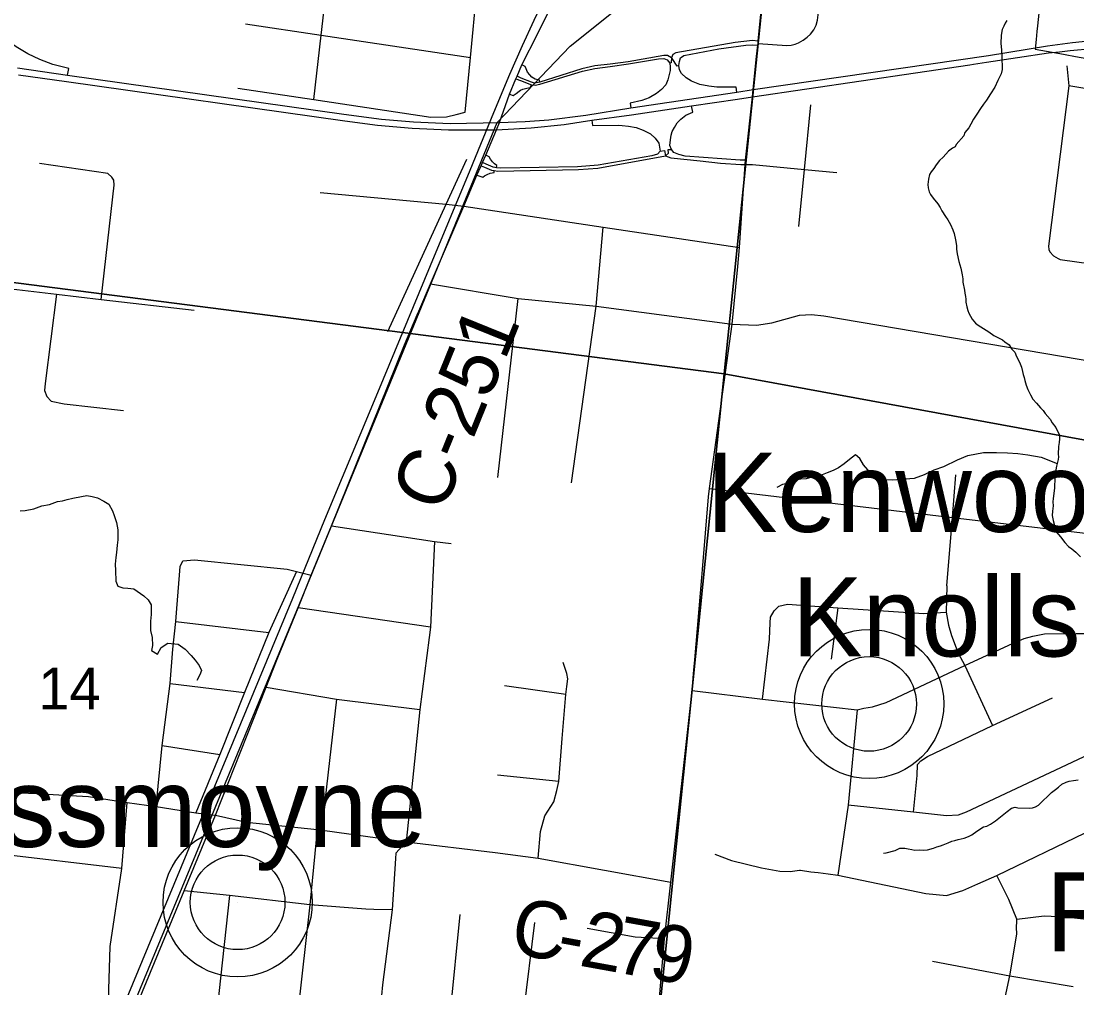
# Model space of a CAD drawing. Extents: x 0 to 34, y -3.9 to 26.2.
# Drawn here: x 6.42 to 7.473, y 18.325 to 19.289 of the extents above; entities that cross this region are included whole.
import ezdxf

# ---------------------------------------------------------------- set-up
doc = ezdxf.new("R2010")
doc.units = 0
for name, color, linetype in [('GM_X_City_Street', 7, 'Continuous'), ('GM_X_County_Road', 7, 'Continuous'), ('GM_X_County_Road_Text', 7, 'Continuous'), ('GM_X_Interchange_Ramps', 7, 'Continuous'), ('GM_X_Minor_River', 7, 'Continuous'), ('GM_X_Rail_Line', 7, 'Continuous'), ('GM_X_Section', 7, 'Continuous'), ('GM_X_Section_Text', 7, 'Continuous'), ('GM_X_State_Route', 7, 'Continuous'), ('GM_X_Township_Road', 7, 'Continuous'), ('GM_X_Unincorporated', 7, 'Continuous'), ('GM_X_Unincorporated_Location', 7, 'Continuous'), ('GM_X_Unincorporated_Text', 7, 'Continuous')]:
    doc.layers.add(name, color=color, linetype=linetype)

msp = doc.modelspace()

# ---------------------------------------------------------------- linework, layer by layer
at = {"layer": 'GM_X_City_Street'}
msp.add_line((6.8951, 18.8339), (6.9155, 19.0126), dxfattribs=at)
for points in [[(7.1548, 19.267), (7.1832, 19.2648), (7.1877, 19.2651), (7.1915, 19.2663), (7.195, 19.2676), (7.1995, 19.2702), (7.2035, 19.2732), (7.2068, 19.2763), (7.2102, 19.2805), (7.2126, 19.2852), (7.2139, 19.29), (7.2147, 19.2955), (7.2286, 19.4323), (7.234, 19.4893)], [(6.8626, 19.1982), (6.8677, 19.2528), (6.8741, 19.3198), (6.8742, 19.321), (6.8806, 19.3716), (6.8938, 19.4782)], [(6.7117, 19.2109), (6.719, 19.2751), (6.7265, 19.3416)], [(6.6434, 19.2864), (6.719, 19.2751), (6.8677, 19.2528)], [(7.4626, 19.2445), (7.4644, 19.2247), (7.4442, 19.0647), (7.4445, 19.0615), (7.4456, 19.059), (7.4493, 19.0551), (7.4538, 19.0523), (7.456, 19.0515), (7.5153, 19.0432), (7.5808, 19.0341)], [(6.6357, 19.2224), (6.7117, 19.2109), (6.8283, 19.1932), (6.8439, 19.1936), (6.8534, 19.1961), (6.8626, 19.1982)], [(7.1062, 18.8228), (7.3484, 18.7941), (7.5235, 18.7734), (7.5317, 18.7746), (7.5375, 18.7779), (7.5412, 18.782), (7.5438, 18.7876), (7.5456, 18.7937), (7.5494, 18.8142), (7.5668, 18.9363), (7.5808, 19.0341), (7.6028, 19.1866), (7.6024, 19.1906), (7.6003, 19.1962), (7.5982, 19.1995), (7.5948, 19.202), (7.5838, 19.2045), (7.4644, 19.2247)], [(7.1954, 19.0844), (7.201, 19.141), (7.2074, 19.2057)], [(6.4996, 19.0115), (6.5126, 19.1255), (6.512, 19.1304), (6.5101, 19.1335), (6.506, 19.137), (6.4379, 19.1472)], [(6.7853, 18.9794), (6.8435, 19.1066), (6.8641, 19.1515)], [(7.1417, 19.1461), (7.1492, 19.1461), (7.201, 19.141), (7.2332, 19.1382)], [(6.7179, 19.1181), (6.8435, 19.1066), (6.8611, 19.1046), (7.0001, 19.0837), (7.1362, 19.0635)], [(6.9687, 18.8286), (6.9931, 19.0047), (7.0001, 19.0837)], [(6.3092, 19.035), (6.3224, 19.0419), (6.3254, 19.0429), (6.3338, 19.0443), (6.3409, 19.0449), (6.3485, 19.0446), (6.3536, 19.0441), (6.358, 19.0431), (6.3655, 19.0405), (6.3726, 19.0363), (6.3843, 19.0283), (6.3878, 19.0264), (6.3929, 19.0251), (6.4096, 19.0221), (6.455, 19.0167), (6.4996, 19.0115), (6.5921, 19.0007)], [(6.8279, 19.0271), (6.9155, 19.0126), (6.9931, 19.0047), (7.1288, 18.987), (7.1531, 18.9858), (7.1683, 18.9883), (7.1959, 18.9957), (7.2078, 18.9965), (7.2201, 18.9953), (7.5668, 18.9363)], [(7.3428, 18.726), (7.3484, 18.7941), (7.3519, 18.8364)]]:
    msp.add_lwpolyline(points, dxfattribs=at)
at = {"layer": 'GM_X_County_Road'}
for p, q in [((7.1548, 19.2692), (7.1598, 19.3192)), ((6.715, 18.4829), (6.7203, 18.4821))]:
    msp.add_line(p, q, dxfattribs=at)
for points in [[(6.9191, 19.2454), (6.9346, 19.2763), (6.9579, 19.3237), (6.9838, 19.3754), (6.9974, 19.4027), (7.0241, 19.4593), (7.0539, 19.5163), (7.1029, 19.6536)], [(7.1494, 19.2172), (7.1498, 19.2209), (7.1532, 19.2538), (7.1543, 19.2651), (7.1548, 19.267), (7.1548, 19.2692)], [(6.8784, 19.1449), (6.8797, 19.148), (6.883, 19.1556), (6.8937, 19.1806), (6.8967, 19.188), (6.9067, 19.2162), (6.9132, 19.2316), (6.9143, 19.2344), (6.9191, 19.2454)], [(7.1344, 19.0444), (7.1362, 19.0635), (7.1417, 19.1461), (7.142, 19.1503), (7.1491, 19.2136), (7.1494, 19.2172)], [(6.8162, 18.9998), (6.8279, 19.0271), (6.8611, 19.1046), (6.8743, 19.1354), (6.8784, 19.1449)], [(7.0992, 18.742), (7.1053, 18.8146), (7.1062, 18.8228), (7.1288, 18.987), (7.1344, 19.0444)], [(6.4488, 18.1059), (6.4496, 18.1078), (6.4657, 18.1464), (6.4931, 18.2096), (6.523, 18.2786), (6.5823, 18.4215), (6.6136, 18.497), (6.664, 18.6248), (6.6751, 18.6528), (6.6959, 18.7039), (6.7091, 18.7364), (6.7291, 18.7856), (6.8019, 18.9663), (6.8146, 18.9962), (6.8162, 18.9998)], [(7.0916, 18.6521), (7.0985, 18.734), (7.0992, 18.742)], [(7.0165, 17.9261), (7.0363, 18.0913), (7.0486, 18.2243), (7.0612, 18.3737), (7.0676, 18.4302), (7.089, 18.6215), (7.0907, 18.6421), (7.0916, 18.6521)], [(6.4173, 18.5195), (6.4192, 18.5194), (6.4349, 18.5188), (6.4628, 18.517), (6.4869, 18.5156), (6.5256, 18.5098), (6.5542, 18.5056), (6.594, 18.4994), (6.6136, 18.497), (6.6443, 18.49), (6.715, 18.4829)], [(6.7203, 18.4821), (6.8036, 18.4705), (6.8923, 18.4598), (6.9354, 18.4542), (7.0676, 18.4302)]]:
    msp.add_lwpolyline(points, dxfattribs=at)
at = {"layer": 'GM_X_Interchange_Ramps'}
for points in [[(7.4353, 19.3035), (7.4333, 19.2843), (7.4327, 19.2787), (7.4319, 19.2707), (7.4309, 19.2612), (7.4592, 19.2561), (7.461, 19.2558), (7.4713, 19.2539), (7.4846, 19.2515)], [(6.466, 19.2354), (6.4671, 19.242), (6.4512, 19.246), (6.4383, 19.251), (6.4265, 19.2564), (6.4148, 19.2634), (6.4054, 19.2701), (6.3984, 19.2761)], [(7.1548, 19.2692), (7.149, 19.2697), (7.1318, 19.2677), (7.0725, 19.2574), (7.0696, 19.2558), (7.0682, 19.2525), (7.068, 19.2477), (7.0665, 19.2472)], [(7.1135, 19.2234), (7.1057, 19.2244), (7.0967, 19.2259), (7.0881, 19.2292), (7.083, 19.2327), (7.0784, 19.2369), (7.0764, 19.2405), (7.0756, 19.2449), (7.0762, 19.2488), (7.0774, 19.2525), (7.0807, 19.255), (7.1155, 19.2614), (7.1425, 19.2653), (7.1489, 19.2655), (7.1543, 19.2651)], [(6.9132, 19.2316), (6.9176, 19.23), (6.9287, 19.2255), (6.9325, 19.2252), (6.937, 19.2263), (6.9796, 19.2392), (6.9919, 19.2419), (7.0073, 19.244), (7.0255, 19.2465), (7.0555, 19.2517), (7.0607, 19.252), (7.0641, 19.2504), (7.0665, 19.2472), (7.0671, 19.2435), (7.0669, 19.2398), (7.0657, 19.2347), (7.0647, 19.2307), (7.0625, 19.2257), (7.0584, 19.2209), (7.0535, 19.2169), (7.0461, 19.2126), (7.0386, 19.21), (7.0271, 19.2074), (7.0276, 19.2025)], [(7.0756, 19.2449), (7.074, 19.2443), (7.0691, 19.2518), (7.0682, 19.2525), (7.0644, 19.255), (7.0607, 19.255), (7.0251, 19.2487), (7.0072, 19.2462), (6.9917, 19.2444), (6.9789, 19.2415), (6.9371, 19.2284), (6.9317, 19.2274), (6.9288, 19.2282), (6.9185, 19.2324), (6.9143, 19.2344)], [(6.9371, 19.2284), (6.9366, 19.2302), (6.9322, 19.2312), (6.9291, 19.2333), (6.9269, 19.2355), (6.9246, 19.2384), (6.9233, 19.2416), (6.9223, 19.2438), (6.9191, 19.2454)], [(6.9067, 19.2162), (6.9105, 19.2149), (6.9133, 19.2171), (6.9163, 19.2193), (6.9177, 19.2202), (6.92, 19.2212), (6.9239, 19.2223), (6.9272, 19.2228), (6.9287, 19.2255)], [(7.1333, 19.2182), (7.1328, 19.2234), (7.1223, 19.2232), (7.1135, 19.2234)], [(7.142, 19.1503), (7.1369, 19.1504), (7.0818, 19.1546), (7.0756, 19.156), (7.0707, 19.1581), (7.0682, 19.1612), (7.0667, 19.1651), (7.0672, 19.1707), (7.068, 19.1754), (7.069, 19.1791), (7.0713, 19.183), (7.0739, 19.1878), (7.0777, 19.1915), (7.0826, 19.1954), (7.0895, 19.1983), (7.0884, 19.2045)], [(6.9888, 19.1905), (6.9894, 19.185), (7.0159, 19.1853), (7.0191, 19.185)], [(7.0191, 19.185), (7.0254, 19.1845), (7.0332, 19.183), (7.0402, 19.1803), (7.0472, 19.1766), (7.0521, 19.1725), (7.0558, 19.1674), (7.0569, 19.1594)], [(6.8784, 19.1449), (6.8817, 19.1435), (6.8887, 19.1406), (6.8915, 19.1401), (6.8951, 19.1395), (6.9756, 19.1411), (6.995, 19.1425), (7.0624, 19.1548), (7.0653, 19.1575), (7.0649, 19.161), (7.0682, 19.1612)], [(7.0569, 19.1594), (7.0542, 19.1565), (7.0486, 19.1547), (6.9952, 19.1456), (6.9746, 19.1439), (6.8982, 19.1424), (6.8937, 19.1429), (6.8906, 19.1435), (6.8836, 19.1465), (6.8797, 19.148)], [(6.8937, 19.1429), (6.894, 19.1453), (6.8918, 19.1468), (6.8898, 19.1487), (6.8878, 19.1515), (6.8866, 19.1538), (6.883, 19.1556)], [(7.0569, 19.1594), (7.0612, 19.1602), (7.0624, 19.1548), (7.0677, 19.1529), (7.0969, 19.1497)], [(7.0969, 19.1497), (7.1171, 19.1474), (7.1375, 19.146), (7.1417, 19.1461)], [(6.8743, 19.1354), (6.88, 19.1336), (6.8819, 19.1349), (6.8846, 19.1363), (6.8873, 19.1374), (6.8915, 19.1381), (6.8915, 19.1401)]]:
    msp.add_lwpolyline(points, dxfattribs=at)
at = {"layer": 'GM_X_Minor_River'}
for points in [[(7.4027, 19.2897), (7.401, 19.2871), (7.3998, 19.2841), (7.3981, 19.2808), (7.3971, 19.2751), (7.3967, 19.2667), (7.3973, 19.2606), (7.3977, 19.2538), (7.3976, 19.2511), (7.3981, 19.2439), (7.398, 19.2408), (7.397, 19.2367), (7.3937, 19.23), (7.3907, 19.2232), (7.3866, 19.2165), (7.3826, 19.2102), (7.3793, 19.2062), (7.3765, 19.2021), (7.3728, 19.1962), (7.3695, 19.1914), (7.3667, 19.1865), (7.365, 19.1828), (7.361, 19.178), (7.3597, 19.1746), (7.3521, 19.1662), (7.3512, 19.1636), (7.3485, 19.1625), (7.3445, 19.1593), (7.3393, 19.1534), (7.3357, 19.1501), (7.3321, 19.1457), (7.33, 19.1423), (7.3272, 19.1387), (7.3256, 19.1361), (7.3246, 19.1315), (7.324, 19.1262), (7.3243, 19.1228), (7.3253, 19.119), (7.3267, 19.1162), (7.3292, 19.1127), (7.3339, 19.1068), (7.3361, 19.1033), (7.3378, 19.0998), (7.3414, 19.0943)], [(7.3414, 19.0943), (7.344, 19.0908), (7.3465, 19.0862), (7.3489, 19.0811), (7.3503, 19.0773), (7.3516, 19.0711), (7.3525, 19.0654), (7.3527, 19.0616), (7.3533, 19.057), (7.3549, 19.0493), (7.3569, 19.0428), (7.3582, 19.0362), (7.3587, 19.032), (7.359, 19.0286), (7.3606, 19.0209), (7.3608, 19.0179), (7.3615, 19.0144), (7.3617, 19.0118), (7.362, 19.0087), (7.3629, 19.0041), (7.3639, 19.0006), (7.365, 18.9979), (7.3682, 18.9917), (7.3714, 18.9878), (7.374, 18.9858), (7.3793, 18.9825), (7.3822, 18.9809), (7.3849, 18.9793), (7.3897, 18.9756), (7.3957, 18.9724), (7.3983, 18.9711), (7.4009, 18.9691), (7.405, 18.9663), (7.4075, 18.9624), (7.4108, 18.9588), (7.4125, 18.9546), (7.4153, 18.9491), (7.4174, 18.9441), (7.4184, 18.9395), (7.419, 18.9368), (7.4201, 18.9337), (7.4207, 18.9307), (7.422, 18.926), (7.4238, 18.9218), (7.4262, 18.9164), (7.4287, 18.9121), (7.4324, 18.9081), (7.4364, 18.9034), (7.439, 18.9007), (7.4411, 18.8979), (7.4459, 18.892), (7.448, 18.8885), (7.4516, 18.8838), (7.4551, 18.876), (7.4554, 18.8726), (7.4548, 18.8688), (7.4543, 18.8647), (7.454, 18.8571), (7.4542, 18.8544), (7.4538, 18.8518), (7.4523, 18.8453), (7.4513, 18.8397), (7.4507, 18.834), (7.4503, 18.8234), (7.4491, 18.8128), (7.4486, 18.8097), (7.4488, 18.8055), (7.4482, 18.8002), (7.448, 18.7961), (7.449, 18.7911), (7.4503, 18.7861), (7.4519, 18.7796), (7.4563, 18.7748), (7.4607, 18.7689), (7.4643, 18.765), (7.4677, 18.7626), (7.4717, 18.7594), (7.4761, 18.7546)], [(7.2747, 18.8323), (7.2886, 18.8317), (7.3012, 18.8326), (7.3107, 18.8332), (7.3206, 18.8368), (7.3302, 18.8416), (7.3398, 18.8448), (7.3536, 18.8514), (7.364, 18.8557), (7.3796, 18.8589), (7.3925, 18.859), (7.4035, 18.8584), (7.4138, 18.8578), (7.4236, 18.8565), (7.4369, 18.8543), (7.4529, 18.848)], [(7.2747, 18.8323), (7.268, 18.836), (7.2641, 18.8415), (7.2597, 18.8466), (7.2562, 18.8528), (7.2517, 18.8564), (7.2459, 18.8517), (7.2404, 18.8474), (7.2349, 18.8435), (7.2295, 18.841), (7.2237, 18.8386), (7.2187, 18.8365), (7.214, 18.8352), (7.2091, 18.8346), (7.2025, 18.8326), (7.1972, 18.8321), (7.1922, 18.8312), (7.1853, 18.8284), (7.1791, 18.8268), (7.1733, 18.824)], [(6.4188, 18.8006), (6.4238, 18.8011), (6.4322, 18.8027), (6.4403, 18.8058), (6.448, 18.807), (6.4561, 18.8101), (6.461, 18.8106), (6.4656, 18.8119), (6.4714, 18.8132), (6.4798, 18.8148), (6.4852, 18.8161), (6.4905, 18.8151), (6.4957, 18.8137), (6.5021, 18.8104), (6.5072, 18.8072), (6.5108, 18.8006), (6.5125, 18.7959), (6.5149, 18.789), (6.5161, 18.7817), (6.5161, 18.7718), (6.5155, 18.7665), (6.5148, 18.759), (6.5143, 18.754), (6.5136, 18.7476), (6.5138, 18.7411), (6.5141, 18.7305), (6.5162, 18.7255), (6.5211, 18.7237), (6.526, 18.7235), (6.532, 18.7229), (6.542, 18.716), (6.5464, 18.712), (6.5493, 18.707), (6.5494, 18.7016), (6.5493, 18.6971), (6.5486, 18.6907), (6.5486, 18.6812), (6.5503, 18.6742), (6.5507, 18.6662), (6.5498, 18.6613), (6.5557, 18.6577), (6.5594, 18.6644), (6.566, 18.6686), (6.5762, 18.6675), (6.5832, 18.6626), (6.5891, 18.6563), (6.5931, 18.6516), (6.5971, 18.6464), (6.5995, 18.6414), (6.5978, 18.6369), (6.5949, 18.6313)], [(7.2796, 18.4593), (7.2823, 18.4596), (7.2912, 18.4619), (7.2959, 18.464), (7.3009, 18.4642), (7.3043, 18.4636), (7.3081, 18.4627), (7.3111, 18.4622), (7.3153, 18.4624), (7.3199, 18.4623), (7.3237, 18.4625), (7.3295, 18.4642), (7.333, 18.4655), (7.3365, 18.4665), (7.3392, 18.4676), (7.3443, 18.4693), (7.3478, 18.471), (7.3509, 18.4717), (7.3543, 18.4727), (7.3601, 18.474), (7.3644, 18.4757), (7.3679, 18.4775), (7.3727, 18.4811), (7.3793, 18.4854), (7.3828, 18.486), (7.3863, 18.4881), (7.3914, 18.4914), (7.3997, 18.4979), (7.4029, 18.5008), (7.4073, 18.504), (7.4111, 18.505), (7.4138, 18.5045), (7.4252, 18.5041), (7.4283, 18.5043), (7.4314, 18.5054), (7.4342, 18.5072), (7.4385, 18.5115), (7.4437, 18.5159), (7.4473, 18.5196), (7.4512, 18.5228), (7.4544, 18.525), (7.4576, 18.5279), (7.4619, 18.53), (7.465, 18.531), (7.4692, 18.5316), (7.4738, 18.5322)]]:
    msp.add_lwpolyline(points, dxfattribs=at)
at = {"layer": 'GM_X_Rail_Line'}
for points in [[(6.4949, 18.2415), (6.5465, 18.3657), (6.6905, 18.7136), (6.7227, 18.792), (6.7755, 18.9187), (6.8279, 19.0453), (6.8674, 19.1406), (6.8911, 19.1979), (6.9071, 19.2364), (6.9196, 19.2649), (6.9312, 19.2902), (6.9677, 19.365), (6.9896, 19.409), (7.0117, 19.4529), (7.0377, 19.5051), (7.0469, 19.5255), (7.0562, 19.5468), (7.0699, 19.5827), (7.0748, 19.5969), (7.098, 19.6602), (7.1178, 19.7152), (7.1979, 19.9367)], [(5.7241, 16.9743), (5.8452, 17.029), (5.873, 17.0335), (5.8979, 17.2837), (6.0426, 17.4881), (6.3175, 17.8683), (6.3835, 17.9611), (6.4086, 18.0098), (6.517, 18.2722), (6.6945, 18.7013), (6.8945, 19.188), (6.9673, 19.2641), (7.0598, 19.3383), (7.1575, 19.4128), (7.1736, 19.4378), (7.1863, 19.6097), (7.204, 19.7377)]]:
    msp.add_lwpolyline(points, dxfattribs=at)
at = {"layer": 'GM_X_Section'}
for points in [[(6.1758, 20.0989), (7.2234, 19.9362), (7.1209, 18.9374), (6.0727, 19.072)], [(7.2234, 19.9362), (8.165, 19.7765), (8.0693, 18.7631), (7.1209, 18.9374)], [(6.0727, 19.072), (7.1209, 18.9374), (7.0185, 17.9275), (5.9742, 18.0677)], [(7.1209, 18.9374), (8.0693, 18.7631), (7.9734, 17.7662), (7.0185, 17.9275)]]:
    msp.add_lwpolyline(points, close=True, dxfattribs=at)
at = {"layer": 'GM_X_State_Route'}
msp.add_line((7.3657, 19.2457), (7.3696, 19.2463), dxfattribs=at)
for points in [[(6.4162, 19.2424), (6.466, 19.2354), (6.7414, 19.1963), (6.7792, 19.1913), (6.811, 19.1886), (6.8476, 19.187), (6.8967, 19.188), (6.9222, 19.189), (6.9461, 19.1908), (6.9828, 19.1954), (7.0276, 19.2025), (7.1333, 19.2182), (7.1498, 19.2209), (7.3844, 19.255), (7.4434, 19.2644), (7.4683, 19.268), (7.4906, 19.2702), (7.5123, 19.2706), (7.536, 19.2688), (7.5641, 19.2656), (7.5924, 19.2586)], [(7.3696, 19.2463), (7.3825, 19.2482), (7.4444, 19.2574), (7.4551, 19.2586)], [(7.4551, 19.2586), (7.4659, 19.2598), (7.4882, 19.262), (7.5099, 19.2624), (7.5356, 19.2618), (7.5617, 19.2574), (7.59, 19.2504), (7.603, 19.2454)], [(6.4171, 19.2357), (6.4648, 19.2289), (6.7425, 19.1898), (6.775, 19.1854), (6.8096, 19.1824), (6.8458, 19.1808), (6.8937, 19.1806), (6.9283, 19.1828), (6.9613, 19.1861), (6.9888, 19.1905), (7.0283, 19.1957), (7.0884, 19.2045), (7.134, 19.2113), (7.1491, 19.2136), (7.3657, 19.2457)]]:
    msp.add_lwpolyline(points, dxfattribs=at)
at = {"layer": 'GM_X_Township_Road'}
for p, q in [((6.832, 18.7699), (6.8307, 18.7414)), ((6.828, 18.6845), (6.6959, 18.7039)), ((7.2342, 18.7039), (7.2275, 18.6528)), ((6.5739, 18.6903), (6.6668, 18.6794)), ((6.5683, 18.6283), (6.6423, 18.6193)), ((6.963, 18.6173), (6.9016, 18.6261)), ((6.5604, 18.5666), (6.6177, 18.5575)), ((6.956, 18.5306), (6.8948, 18.5369)), ((6.7203, 18.4821), (6.715, 18.4829)), ((6.52, 18.444), (6.3904, 18.4591)), ((6.7897, 18.4025), (6.7715, 18.403)), ((6.8422, 18.2465), (6.8577, 18.3979)), ((6.9135, 18.2387), (6.932, 18.3899)), ((7.0321, 18.3754), (6.9843, 18.3839)), ((7.0612, 18.3737), (7.0321, 18.3754))]:
    msp.add_line(p, q, dxfattribs=at)
for points in [[(6.455, 19.0167), (6.4435, 18.9277), (6.4431, 18.9206), (6.4452, 18.9147), (6.4497, 18.91), (6.4625, 18.9073), (6.5217, 18.9006)], [(6.7291, 18.7856), (6.832, 18.7699), (6.8485, 18.7679)], [(6.5739, 18.6903), (6.5749, 18.7031), (6.5777, 18.7364), (6.5783, 18.7452), (6.5809, 18.7509)], [(6.5809, 18.7509), (6.5926, 18.7517), (6.685, 18.7424), (6.6943, 18.74), (6.7091, 18.7364)], [(6.6943, 18.74), (6.6668, 18.6794), (6.6423, 18.6193), (6.6177, 18.5575), (6.594, 18.4994)], [(6.8307, 18.7414), (6.828, 18.6845), (6.8267, 18.6742)], [(7.3428, 18.726), (7.3423, 18.6997), (7.3447, 18.6865), (7.3475, 18.6762), (7.3541, 18.6586), (7.3607, 18.6464), (7.3886, 18.5864)], [(7.1592, 18.6127), (7.166, 18.6726), (7.1666, 18.6889), (7.1672, 18.6947), (7.1707, 18.7009), (7.1752, 18.7055), (7.184, 18.7077), (7.2342, 18.7039), (7.3198, 18.6983), (7.3423, 18.6997)], [(6.5542, 18.5056), (6.5604, 18.5666), (6.5683, 18.6283), (6.5711, 18.6628), (6.5739, 18.6903)], [(6.8267, 18.6742), (6.8174, 18.6024), (6.8036, 18.4705), (6.7935, 18.459), (6.7932, 18.4539)], [(7.089, 18.6215), (7.1592, 18.6127), (7.2534, 18.6022), (7.2602, 18.6038), (7.2687, 18.6052), (7.2825, 18.6095), (7.3607, 18.6464), (7.4091, 18.6688), (7.4201, 18.6734), (7.4287, 18.6756), (7.4403, 18.6778), (7.472, 18.6782), (7.4989, 18.6782)], [(6.9354, 18.4542), (6.9375, 18.4809), (6.9419, 18.4965), (6.9508, 18.5102), (6.954, 18.5218), (6.956, 18.5306), (6.9592, 18.5736), (6.963, 18.6173), (6.964, 18.6255), (6.9648, 18.6329), (6.964, 18.6383), (6.9602, 18.6494)], [(6.664, 18.6248), (6.7342, 18.6129), (6.8174, 18.6024)], [(6.7342, 18.6129), (6.7229, 18.5137), (6.7203, 18.4821)], [(7.3098, 18.5002), (7.3132, 18.5366), (7.3138, 18.5477), (7.317, 18.5513), (7.3236, 18.5557), (7.3886, 18.5864), (7.4484, 18.6141)], [(7.2534, 18.6022), (7.2446, 18.507), (7.2342, 18.4372)], [(7.4902, 18.5602), (7.3623, 18.5), (7.3543, 18.4971), (7.3427, 18.4963), (7.3098, 18.5002), (7.2446, 18.507)], [(6.5057, 18.2801), (6.5086, 18.3659), (6.52, 18.444), (6.5256, 18.5098)], [(7.3739, 18.4286), (7.3926, 18.437), (7.4807, 18.4796), (7.4972, 18.4897)], [(6.715, 18.4829), (6.7077, 18.4075), (6.6913, 18.2622), (6.6849, 18.1897), (6.6732, 18.0815), (6.6619, 17.9756)], [(7.1116, 18.4582), (7.128, 18.4519), (7.1581, 18.4444), (7.1762, 18.4412), (7.1866, 18.441), (7.1961, 18.4421)], [(6.7932, 18.4539), (6.7897, 18.4025), (6.7801, 18.3277), (6.773, 18.2534), (6.7609, 18.1478), (6.7418, 17.9647)], [(7.1961, 18.4421), (7.1971, 18.4422), (7.2071, 18.4406), (7.2147, 18.4398), (7.2244, 18.4385)], [(7.2244, 18.4385), (7.2342, 18.4372), (7.322, 18.4189), (7.3425, 18.4169), (7.3589, 18.4219), (7.3739, 18.4286)], [(7.392, 18.2734), (7.4056, 18.3367), (7.4127, 18.3783), (7.4128, 18.3808), (7.4125, 18.3831), (7.4127, 18.3933), (7.4046, 18.4131), (7.3926, 18.437)], [(6.6274, 18.4169), (6.6114, 18.2703), (6.6035, 18.1972), (6.5899, 18.0899), (6.579, 17.9867)], [(6.7715, 18.403), (6.7633, 18.4032), (6.7077, 18.4075), (6.6274, 18.4169), (6.5823, 18.4215)], [(7.4127, 18.3933), (7.4399, 18.3965), (7.4608, 18.3955), (7.4885, 18.3925)], [(7.3286, 18.3515), (7.4056, 18.3367), (7.469, 18.3263)]]:
    msp.add_lwpolyline(points, dxfattribs=at)
at = {"layer": 'GM_X_Unincorporated'}
for centre, radius in [((7.2654, 18.608), 0.0744), ((7.2654, 18.608), 0.0472), ((6.6356, 18.4101), 0.0744), ((6.6356, 18.4101), 0.0472)]:
    msp.add_circle(centre, radius, dxfattribs=at)
at = {"layer": 'GM_X_Unincorporated_Location'}
for p, q in [((7.2654, 18.608), (7.2654, 18.608)), ((6.6356, 18.4101), (6.6356, 18.4101))]:
    msp.add_line(p, q, dxfattribs=at)

# ---------------------------------------------------------------- texts
at = {"layer": 'GM_X_County_Road_Text'}
for s, height, rotation, p in [('C-251', 0.05682, 67.947, (6.8401, 18.7969)), ('C', 0.0568, 349.0759, (6.9054, 18.3603)), ('2', 0.0568, 349.7336, (6.9749, 18.3472)), ('7', 0.0568, 349.7572, (7.0093, 18.3409)), ('9', 0.0568, 349.7697, (7.0438, 18.3347)), ('-', 0.0568, 349.6586, (6.9518, 18.3514))]:
    msp.add_text(s, height=height, rotation=rotation, dxfattribs=at).set_placement(p)
at = {"layer": 'GM_X_Section_Text'}
msp.add_text('14', height=0.04186, rotation=0, dxfattribs=at).set_placement((6.4368, 18.6025))
at = {"layer": 'GM_X_Unincorporated_Text'}
for s, p in [('Kenwood', (7.1035, 18.7796)), ('Knolls', (7.1885, 18.6554)), ('Rossmoyne', (6.266, 18.4654)), ('Raiders', (7.4418, 18.3612))]:
    msp.add_text(s, height=0.07898, rotation=0, dxfattribs=at).set_placement(p)

doc.saveas('drawing.dxf')
